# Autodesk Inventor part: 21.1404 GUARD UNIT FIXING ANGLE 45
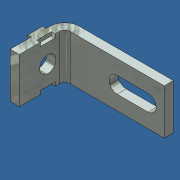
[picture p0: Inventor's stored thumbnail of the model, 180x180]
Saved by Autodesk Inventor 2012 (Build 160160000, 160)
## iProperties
Created: 2007-01
Part Number: 21.1404 GUARD UNIT FIXING ANGLE 45
Material: Steel
Document SubType Name: Modeling
Designer: Andy Moles
Density: 7.85 g/cm^3
Author: Andy Moles
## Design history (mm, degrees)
sketch "Sketch1"
  geometry: L1 (30, 30)-(30, 8); L2 (22, 0)-(-30, 0); L3 (-30, 5)-(22, 5); L4 (25, 8)-(25, 30); L5 (-30, 0)-(-30, 5); L6 (30, 30)-(25, 30); A1 r 8 centre (22, 8) between (22, 0) and (30, 8); A2 r 3 centre (22, 8) between (22, 5) and (25, 8); 1 further point
  constraints: 12 end point, 4 point on circle, 3 perpendicular, 2 centre point, 2 tangent, 1 parallel, 1 vertical, 2 other
  dimensions: "d0" = 60 distance from line of L2.end L1; "d1" = 8 radius of A1; "d2" = 30 distance from line of L1.start L2; "d3" = 5 distance between parallel lines of L2 L3; "d21" = 30 distance from line of point (0, 0) L1; "d22" = 0 distance from line of point (0, 0) L2
extrude "Extrusion1" join sketch "Sketch1" stored distance "d4" = 25; taper "d5" = 0 deg
sketch "Sketch2"
  geometry: L1 (0, 25)-(0, 0) reference; L2 (30, 25)-(30, 0) reference; C1 r 4.5 at (15.7, 12.5); 2 further points
  constraints: 1 centre point, 1 horizontal alignment, 1 midpoint
  dimensions: "d6" = 9 diameter of C1; "d7" = 14.3 distance from line of C1.centre L2
extrude "Extrusion2" cut sketch "Sketch2" distance "d8" = 25; taper "d9" = 0 deg
sketch "Sketch3"
  geometry: L1 (52, 0)-(52, -25) reference; L2 (26, -8)-(43, -8); L3 (26, -17)-(43, -17); A1 r 4.5 centre (26, -12.5) between (26, -8) and (26, -17); A2 r 4.5 centre (43, -12.5) between (43, -17) and (43, -8); 2 further points
  constraints: 4 end point, 4 point on circle, 4 tangent, 2 centre point, 2 horizontal alignment, 1 equal radius, 1 midpoint
  dimensions: "d10" = 4.5 radius of A2; "d11" = 17 distance of A1.centre A2.centre; "d12" = 9 distance from line of A2.centre L1
extrude "Extrusion3" cut sketch "Sketch3" distance "d13" = 25; taper "d14" = 0 deg
sketch "Sketch4"
  geometry: L1 (22, 25)-(0, 25) reference; L2 (0, 0)-(22, 0) reference; L3 (11.6, 25)-(19.8, 25); L4 (19.8, 25)-(19.8, 23); L5 (19.8, 23)-(11.6, 23); L6 (11.6, 23)-(11.6, 25); L7 (11.6, 2)-(19.8, 2); L8 (19.8, 2)-(19.8, 0); L9 (19.8, 0)-(11.6, 0); L10 (11.6, 0)-(11.6, 2); C1 r 4.5 at (15.7, 12.5) reference; 3 further points
  constraints: 16 end point, 4 parallel, 2 collinear, 2 equal length, 2 horizontal, 2 midpoint, 2 perpendicular, 2 vertical alignment
  dimensions: "d15" = 8.2 distance of L3.start L3.end; "d16" = 2 distance of L5.end L3.start
extrude "Extrusion4" cut sketch "Sketch4" distance "d17" = 2; taper "d18" = 0 deg
sketch "Sketch5"
  geometry: L1 (10.4, 25)-(10.4, 23) reference; L2 (10.4, 23)-(2.2, 23) reference; L3 (2.2, 23)-(2.2, 25) reference; L4 (10.4, 25)-(2.2, 25) reference; L5 (10.4, 2)-(10.4, 0) reference; L6 (2.2, 0)-(10.4, 0) reference; L7 (2.2, 0)-(2.2, 2) reference; L8 (2.2, 2)-(10.4, 2) reference; 1 further point
extrude "Extrusion5" join sketch "Sketch5" distance "d19" = 2; taper "d20" = 0 deg
body "Solid1"
node "Projected Loop1"
node "Projected Loop2"
